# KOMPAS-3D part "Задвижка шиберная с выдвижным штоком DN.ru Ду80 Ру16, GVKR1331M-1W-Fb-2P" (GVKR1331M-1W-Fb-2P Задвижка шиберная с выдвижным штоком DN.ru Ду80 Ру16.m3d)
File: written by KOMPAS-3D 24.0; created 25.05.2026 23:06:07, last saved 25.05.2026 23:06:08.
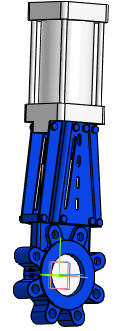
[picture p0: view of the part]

Document properties: Автор: R2D2; Полное имя файла: E:\Работа\Зайцев\GVKR1331M-1W-Fb-2P Задвижка шиберная с выдвижным штоком DN.ru Ду50-300 Ру16-10-6 с пневмоприводом\исходные материалы\DN80\DN80\GVKR1331M-1W-Fb-2P Задвижка шиберная с выдвижным штоком DN.ru Ду80 Ру16.m3d

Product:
- Part/product: Задвижка шиберная с выдвижным штоком DN.ru Ду80 Ру16  | designation GVKR1331M-1W-Fb-2P
    Масса: 12
    Раздел спецификации: Прочие изделия
    Примечание: D040-08793

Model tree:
1. Операция без истории:1

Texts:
  GVKR1331M-1W-Fb-2P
